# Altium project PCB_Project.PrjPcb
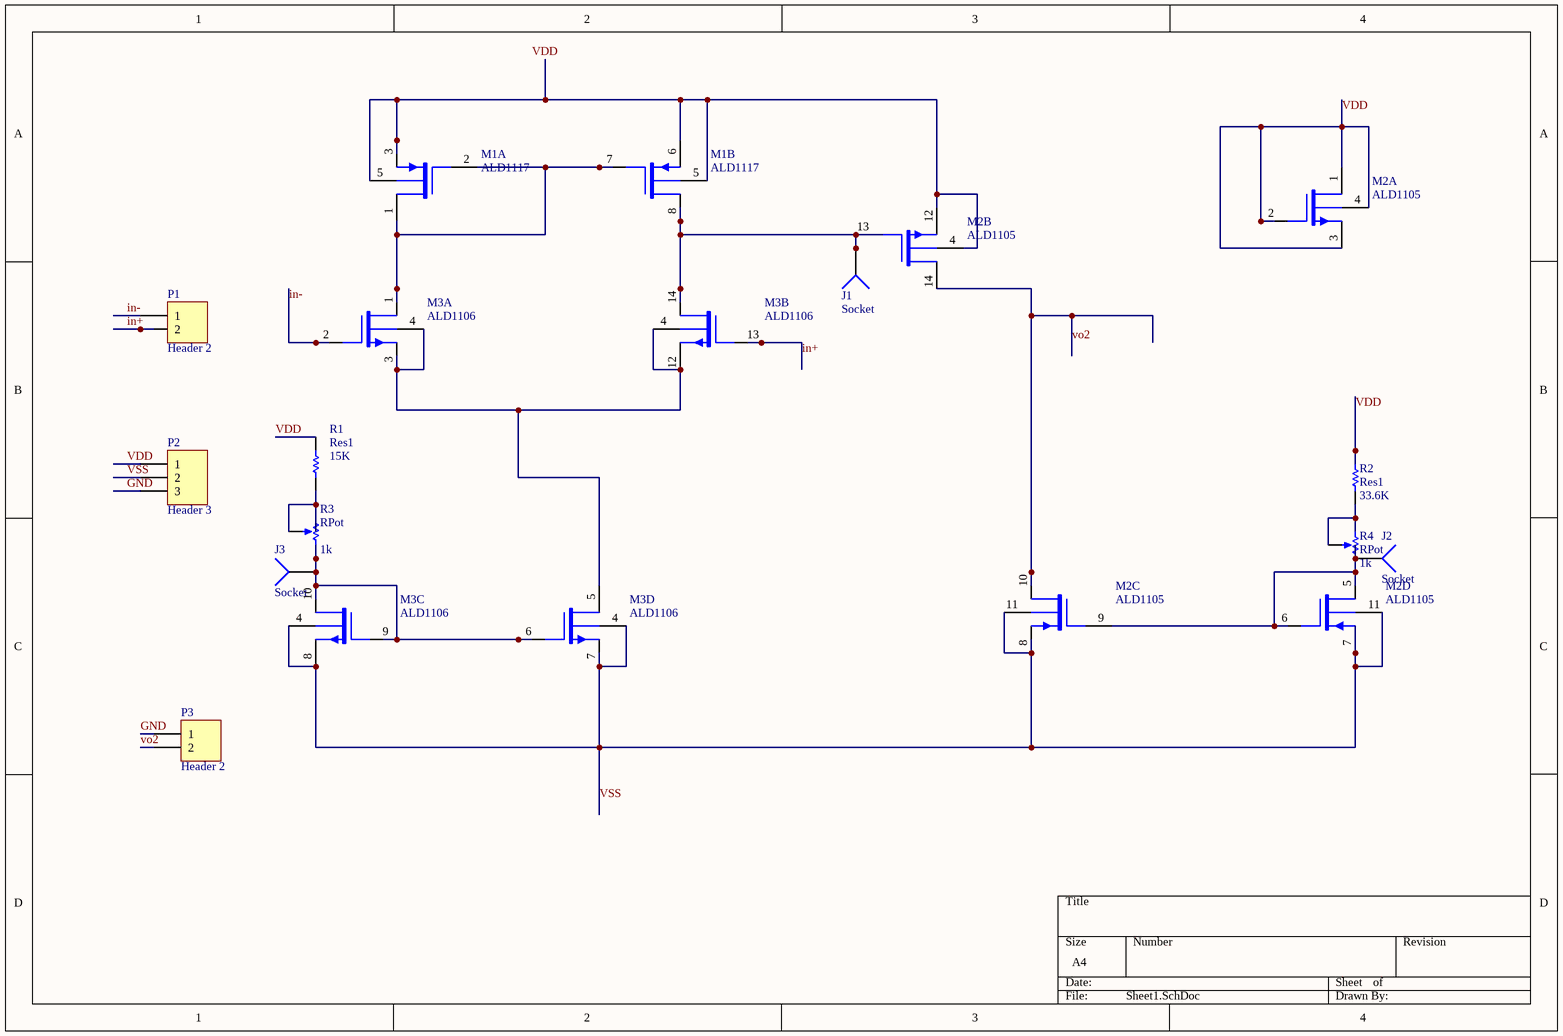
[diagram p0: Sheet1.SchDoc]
1 sheet, 13 parts. Net scope: global (net labels, ports and power ports of the same name join across sheets).
Board file: PCB1.PcbDoc

## Sheet Sheet1.SchDoc
size A4

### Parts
J1  Socket  [PIN1]
J2  Socket  [PIN1]
J3  Socket  [PIN1]
M1  ALD1117  [DIP-8]  (parts A,B of 2)
M2  ALD1105  [DIP-14]  (parts A,B,C,D of 4)
M3  ALD1106  [DIP-14]  (parts A,B,C,D of 4)
P1  Header 2  [HDR1X2]
P2  Header 3  [HDR1X3]
P3  Header 2  [HDR1X2]
R1  Res1  value 15K  [AXIAL-0.3]
R2  Res1  value 33.6K  [AXIAL-0.3]
R3  RPot  value 1k  [VR5]
R4  RPot  value 1k  [VR5]

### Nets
GND: P2.3 P3.1
in+: M3.13(GN2) P1.2
in-: M3.2(GN1) P1.1
VDD: M2.1(DN1) M2.2(GN1) M2.3(SN1) M2.4(V-) P2.1 R1.2 R2.2
vo2: M2.10(DP2) M2.14(DN2) P3.2
VSS: M2.7(SP1) M2.8(SP2) M2.11(V+) M3.4(V-) M3.7(SN4) M3.8(SN3) P2.2
NetJ1_1: J1.1 M1.8(DP2) M2.13(GN2) M3.14(DN2)
NetJ2_1: J2.1 M2.5(DP1) M2.6(GP1) M2.9(GP2) R4.3(BOT)
NetJ3_1: J3.1 M3.6(GN4) M3.9(GN3) M3.10(DN3) R3.3(BOT)
NetM1_1: M1.1(DP1) M1.2(GP1) M1.7(GP2) M3.1(DN1)
NetM1_3: M1.3(SP1) M1.5(V+) M1.6(SP2) M2.4(V-) M2.12(SN2)
NetM3_3: M3.3(SN1) M3.4(V-) M3.5(DN4) M3.12(SN2)
NetR1_1: R1.1 R3.1(TOP) R3.2(TAP)
NetR2_1: R2.1 R4.1(TOP) R4.2(TAP)

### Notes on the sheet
- Labels drawn without touching a wire or pin: VDD

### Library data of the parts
M1 = ALD1117: Dual P-channel matched MOSFET array
M2 = ALD1105: Dual P-channel and dual N-channel matched MOSFET array
M3 = ALD1106: Quad N-channel matched MOSFET array
P1 P3 = Header 2: Header, 2-Pin
P2 = Header 3: Header, 3-Pin
R1 R2 = Res1: Resistor
R3 R4 = RPot: Potentiometer; Sim Note: Enter the Resistance value and the set point into parameter fields.; Set Position: 0.5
